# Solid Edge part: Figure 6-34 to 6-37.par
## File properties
Author: CADCIM
Template: Iso Part.par
Last saved by: CADCIM
Revision: 6
Application: Solid Edge
Accuracy: 0.990
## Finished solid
Body 1: solid body, 15 faces, 39 edges, 26 vertices.
  Faces by surface: plane 15
  Edges by curve: line 39
Bounding box of the edges (mm): 50.000 x 50.000 x 38.268, from (0, -25, 0) to (50, 25, 38.268).
Planar faces by outward normal: +x 3, +y 2, +z 2, -x 2, -y 2, -z 1, oblique 3
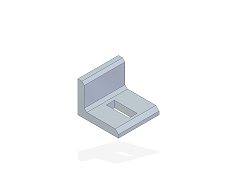
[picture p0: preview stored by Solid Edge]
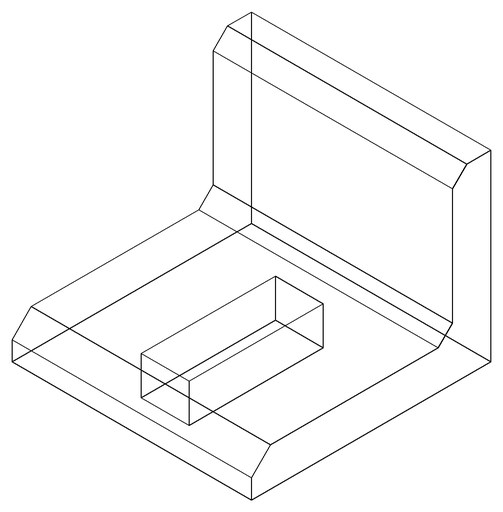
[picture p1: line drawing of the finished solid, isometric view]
